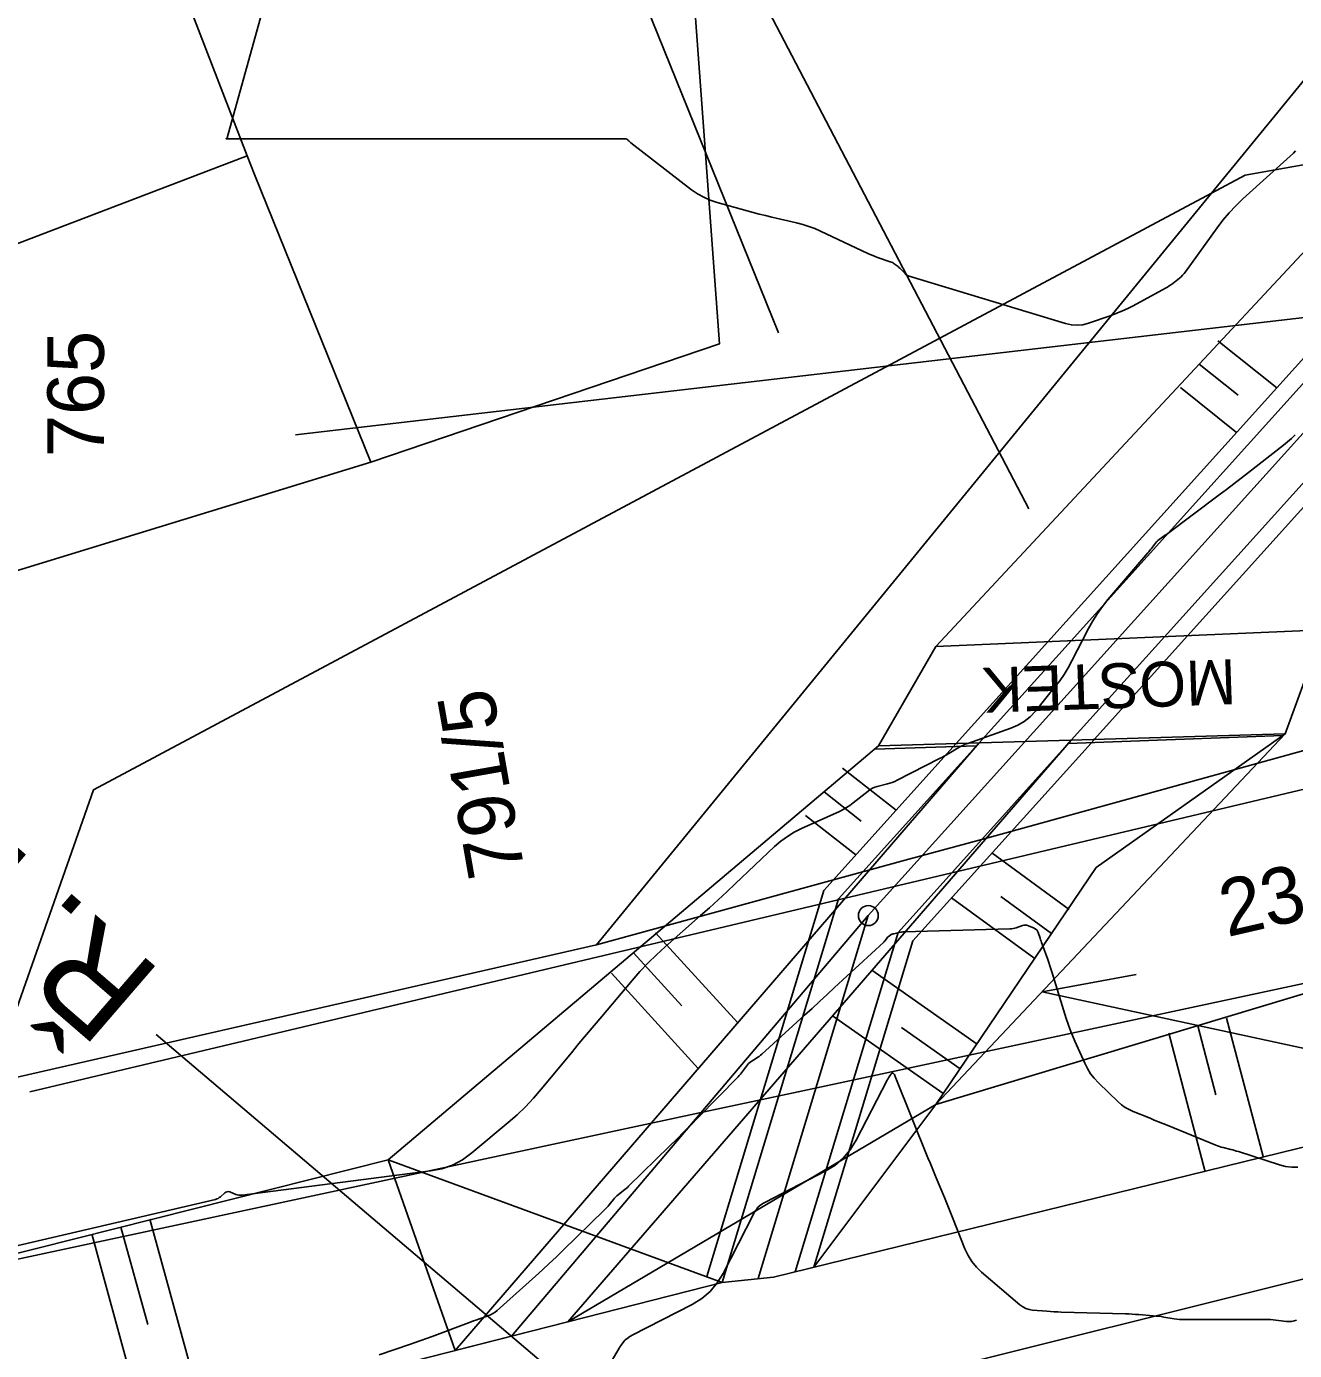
# Model space of a CAD drawing. Extents: x -534481 to -534262, y -1190577 to -1190138.
# Drawn here: x -534420.76 to -534401.7, y -1190524.99 to -1190505.1 of the extents above; entities that cross this region are included whole.
import ezdxf

# ---------------------------------------------------------------- set-up
doc = ezdxf.new("R2010")
doc.units = 0
for name, color, linetype in [('_přístup', 7, 'Continuous'), ('Bonity', 7, 'Continuous'), ('Definiční body', 7, 'Continuous'), ('Polygon budovy', 7, 'Continuous'), ('Vrstva 18', 7, 'Continuous'), ('Vrstva 19', 7, 'Continuous'), ('Vrstva 31', 7, 'Continuous'), ('Vrstva 32', 7, 'Continuous'), ('Vrstva 35', 7, 'Continuous'), ('Vrstva 36', 7, 'Continuous'), ('Vrstva 37', 7, 'Continuous'), ('Vrstva 41', 7, 'Continuous'), ('Vrstva 45', 7, 'Continuous'), ('Vrstva 58', 7, 'Continuous'), ('Značky bodu BP', 7, 'Continuous')]:
    doc.layers.add(name, color=color, linetype=linetype)

msp = doc.modelspace()

# ---------------------------------------------------------------- linework, layer by layer
at = {"layer": '_přístup'}
msp.add_lwpolyline([(-534437.347, -1190471.884), (-534433.314, -1190474.1), (-534423.794, -1190480.783), (-534415.053, -1190495.863), (-534409.457, -1190509.706)], dxfattribs=at)
at = {"layer": 'Bonity'}
for p, q in [((-534408.105, -1190518.46), (-534413.469, -1190524.777)), ((-534422.24, -1190529.075), (-534398.624, -1190523.185))]:
    msp.add_line(p, q, dxfattribs=at)
for points in [[(-534408.105, -1190518.46), (-534393.616, -1190502.389), (-534391.346, -1190496.962), (-534392.763, -1190488.017), (-534396.655, -1190477.752), (-534402.513, -1190464.283), (-534404.757, -1190456.741), (-534408.311, -1190433.088), (-534409.248, -1190427.879), (-534409.316, -1190416.054), (-534409.076, -1190409.418), (-534409.868, -1190391.439)], [(-534409.76, -1190523.914), (-534408.105, -1190518.46)]]:
    msp.add_lwpolyline(points, dxfattribs=at)
at = {"layer": 'Definiční body'}
for p, q in [((-534402.95, -1190507.61), (-534395.53, -1190498.55)), ((-534425.14, -1190509.99), (-534417.44, -1190507.05)), ((-534412.19, -1190518.9), (-534402.95, -1190507.61)), ((-534423.46, -1190514.06), (-534415.58, -1190511.65)), ((-534421.3, -1190520.98), (-534412.19, -1190518.9))]:
    msp.add_line(p, q, dxfattribs=at)
for points in [[(-534417.44, -1190507.05), (-534418.68, -1190503.83), (-534419, -1190502.99), (-534420.25, -1190499.72)], [(-534415.58, -1190511.65), (-534410.34, -1190509.87), (-534410.71, -1190504.84), (-534404.16, -1190502.37)], [(-534389.63, -1190505.06), (-534396.5, -1190506.28), (-534398.08, -1190506.56), (-534402.44, -1190507.34), (-534402.95, -1190507.61)], [(-534415.58, -1190511.65), (-534417.33, -1190507.33), (-534417.44, -1190507.05)], [(-534421.3, -1190520.98), (-534419.75, -1190516.57), (-534402.95, -1190507.61)], [(-534378.833, -1190515.085), (-534383.27, -1190515.56), (-534409.16, -1190521.11), (-534410.57, -1190521.41), (-534422.34, -1190523.93)], [(-534401.56, -1190515.98), (-534406.2, -1190517.26), (-534407.55, -1190517.63), (-534412.19, -1190518.9)]]:
    msp.add_lwpolyline(points, dxfattribs=at)
at = {"layer": 'Vrstva 18'}
for points in [[(-534416.759, -1190503.239), (-534417.74, -1190506.779), (-534417.742, -1190506.785), (-534417.745, -1190506.789), (-534417.75, -1190506.791), (-534417.756, -1190506.792), (-534417.737, -1190506.792), (-534417.73, -1190506.792), (-534411.753, -1190506.792), (-534411.748, -1190506.792), (-534411.744, -1190506.793), (-534411.739, -1190506.795), (-534411.736, -1190506.797), (-534411.721, -1190506.809), (-534411.713, -1190506.815), (-534411.706, -1190506.821), (-534411.691, -1190506.837), (-534411.683, -1190506.844), (-534411.675, -1190506.851), (-534410.762, -1190507.556), (-534410.673, -1190507.618), (-534410.579, -1190507.671), (-534410.48, -1190507.714), (-534410.377, -1190507.748), (-534409.928, -1190507.873), (-534409.835, -1190507.899), (-534409.743, -1190507.923), (-534409.65, -1190507.946), (-534409.556, -1190507.968), (-534409.183, -1190508.055), (-534409.091, -1190508.079), (-534409, -1190508.107), (-534408.911, -1190508.141), (-534408.823, -1190508.179), (-534408.11, -1190508.515), (-534408.075, -1190508.531), (-534408.039, -1190508.546), (-534408.002, -1190508.56), (-534407.965, -1190508.574), (-534407.776, -1190508.639), (-534407.76, -1190508.645), (-534407.744, -1190508.652), (-534407.729, -1190508.661), (-534407.715, -1190508.671), (-534407.659, -1190508.712), (-534407.646, -1190508.723), (-534407.632, -1190508.734), (-534407.62, -1190508.746), (-534407.607, -1190508.758), (-534407.552, -1190508.817), (-534407.539, -1190508.829), (-534407.524, -1190508.84), (-534407.507, -1190508.849), (-534407.489, -1190508.856), (-534405.14, -1190509.568), (-534405.053, -1190509.588), (-534404.967, -1190509.593), (-534404.882, -1190509.584), (-534404.796, -1190509.562), (-534404.454, -1190509.444), (-534404.37, -1190509.413), (-534404.287, -1190509.378), (-534404.205, -1190509.34), (-534404.125, -1190509.299), (-534403.639, -1190509.037), (-534403.611, -1190509.021), (-534403.583, -1190509.003), (-534403.557, -1190508.985), (-534403.531, -1190508.965), (-534403.429, -1190508.885), (-534403.405, -1190508.864), (-534403.382, -1190508.841), (-534403.36, -1190508.817), (-534403.34, -1190508.792), (-534402.865, -1190508.131), (-534402.777, -1190508.015), (-534402.683, -1190507.903), (-534402.583, -1190507.797), (-534402.477, -1190507.696), (-534401.716, -1190507.007), (-534401.683, -1190506.973)], [(-534415.454, -1190525.058), (-534414.999, -1190524.903), (-534414.913, -1190524.873), (-534414.829, -1190524.843), (-534414.744, -1190524.813), (-534414.659, -1190524.781), (-534414.112, -1190524.577), (-534414.075, -1190524.563), (-534414.038, -1190524.55), (-534414.001, -1190524.536), (-534413.964, -1190524.523), (-534413.817, -1190524.471), (-534413.781, -1190524.456), (-534413.747, -1190524.438), (-534413.715, -1190524.417), (-534413.685, -1190524.392), (-534413.109, -1190523.879), (-534413.003, -1190523.784), (-534412.899, -1190523.688), (-534412.796, -1190523.591), (-534412.695, -1190523.492), (-534412.069, -1190522.88), (-534412.051, -1190522.862), (-534412.034, -1190522.843), (-534412.017, -1190522.824), (-534412, -1190522.805), (-534411.935, -1190522.724), (-534411.918, -1190522.705), (-534411.901, -1190522.687), (-534411.883, -1190522.67), (-534411.863, -1190522.654), (-534411.783, -1190522.592), (-534411.763, -1190522.576), (-534411.744, -1190522.56), (-534411.725, -1190522.543), (-534411.707, -1190522.525), (-534411.092, -1190521.924), (-534410.984, -1190521.818), (-534410.876, -1190521.711), (-534410.769, -1190521.604), (-534410.663, -1190521.495), (-534410.062, -1190520.881), (-534410.045, -1190520.862), (-534410.028, -1190520.843), (-534410.012, -1190520.824), (-534409.997, -1190520.803), (-534409.936, -1190520.72), (-534409.921, -1190520.701), (-534409.904, -1190520.684), (-534409.886, -1190520.668), (-534409.866, -1190520.654), (-534409.784, -1190520.602), (-534409.764, -1190520.589), (-534409.744, -1190520.575), (-534409.725, -1190520.559), (-534409.707, -1190520.543), (-534409.063, -1190519.957), (-534408.95, -1190519.854), (-534408.837, -1190519.75), (-534408.725, -1190519.646), (-534408.612, -1190519.542), (-534407.874, -1190518.859), (-534407.866, -1190518.851), (-534407.859, -1190518.844), (-534407.853, -1190518.836), (-534407.847, -1190518.828), (-534407.822, -1190518.793), (-534407.816, -1190518.786), (-534407.809, -1190518.779), (-534407.801, -1190518.773), (-534407.793, -1190518.767), (-534407.76, -1190518.746), (-534407.751, -1190518.741), (-534407.742, -1190518.737), (-534407.733, -1190518.734), (-534407.724, -1190518.732), (-534407.639, -1190518.713), (-534407.621, -1190518.71), (-534407.604, -1190518.707), (-534407.586, -1190518.705), (-534407.569, -1190518.705), (-534405.977, -1190518.661), (-534405.953, -1190518.659), (-534405.929, -1190518.656), (-534405.905, -1190518.65), (-534405.882, -1190518.643), (-534405.788, -1190518.61), (-534405.766, -1190518.604), (-534405.743, -1190518.602), (-534405.721, -1190518.605), (-534405.699, -1190518.613), (-534405.611, -1190518.651), (-534405.591, -1190518.662), (-534405.575, -1190518.676), (-534405.563, -1190518.693), (-534405.554, -1190518.714), (-534405.525, -1190518.801), (-534405.517, -1190518.823), (-534405.51, -1190518.844), (-534405.502, -1190518.866), (-534405.494, -1190518.888), (-534405.408, -1190519.121), (-534405.391, -1190519.167), (-534405.375, -1190519.214), (-534405.36, -1190519.261), (-534405.345, -1190519.307), (-534405.131, -1190520.004), (-534405.103, -1190520.091), (-534405.072, -1190520.177), (-534405.038, -1190520.261), (-534405.002, -1190520.345), (-534404.853, -1190520.678), (-534404.812, -1190520.759), (-534404.764, -1190520.835), (-534404.709, -1190520.905), (-534404.647, -1190520.971), (-534404.35, -1190521.257), (-534404.299, -1190521.302), (-534404.244, -1190521.341), (-534404.186, -1190521.375), (-534404.124, -1190521.403), (-534403.87, -1190521.505), (-534403.807, -1190521.531), (-534403.743, -1190521.557), (-534403.68, -1190521.582), (-534403.616, -1190521.608), (-534402.884, -1190521.909), (-534402.857, -1190521.919), (-534402.829, -1190521.929), (-534402.801, -1190521.938), (-534402.772, -1190521.945), (-534402.658, -1190521.973), (-534402.629, -1190521.98), (-534402.601, -1190521.988), (-534402.573, -1190521.997), (-534402.544, -1190522.005), (-534401.926, -1190522.206), (-534401.834, -1190522.229), (-534401.742, -1190522.239), (-534401.649, -1190522.237)]]:
    msp.add_lwpolyline(points, dxfattribs=at)
at = {"layer": 'Vrstva 19'}
for points in [[(-534401.691, -1190511.239), (-534401.747, -1190511.292), (-534401.805, -1190511.343), (-534401.865, -1190511.392), (-534402.393, -1190511.807), (-534402.502, -1190511.892), (-534402.611, -1190511.976), (-534402.721, -1190512.06), (-534402.831, -1190512.142), (-534403.626, -1190512.734), (-534403.652, -1190512.753), (-534403.678, -1190512.773), (-534403.754, -1190512.827), (-534403.757, -1190512.83), (-534403.76, -1190512.834), (-534403.772, -1190512.848), (-534403.851, -1190512.946), (-534403.864, -1190512.962), (-534403.878, -1190512.979), (-534403.892, -1190512.996), (-534403.906, -1190513.012), (-534404.505, -1190513.714), (-534404.586, -1190513.816), (-534404.662, -1190513.922), (-534404.731, -1190514.032), (-534404.794, -1190514.146), (-534405.045, -1190514.636), (-534405.101, -1190514.739), (-534405.162, -1190514.838), (-534405.228, -1190514.934), (-534405.3, -1190515.026), (-534405.595, -1190515.389), (-534405.674, -1190515.473), (-534405.761, -1190515.544), (-534405.858, -1190515.602), (-534405.964, -1190515.647), (-534406.612, -1190515.873), (-534406.649, -1190515.887), (-534406.686, -1190515.903), (-534406.722, -1190515.921), (-534406.757, -1190515.941), (-534406.896, -1190516.025), (-534406.931, -1190516.045), (-534406.966, -1190516.065), (-534407.001, -1190516.085), (-534407.037, -1190516.103), (-534407.673, -1190516.428), (-534407.709, -1190516.445), (-534407.745, -1190516.459), (-534407.781, -1190516.472), (-534407.819, -1190516.483), (-534407.971, -1190516.521), (-534408.008, -1190516.533), (-534408.043, -1190516.548), (-534408.077, -1190516.567), (-534408.108, -1190516.59), (-534408.332, -1190516.769), (-534408.381, -1190516.805), (-534408.431, -1190516.838), (-534408.484, -1190516.868), (-534408.538, -1190516.895), (-534409.107, -1190517.152), (-534409.217, -1190517.208), (-534409.322, -1190517.272), (-534409.42, -1190517.344), (-534409.514, -1190517.425), (-534410.104, -1190517.984), (-534410.233, -1190518.105), (-534410.363, -1190518.224), (-534410.494, -1190518.343), (-534410.626, -1190518.46), (-534411.159, -1190518.929), (-534411.29, -1190519.048), (-534411.416, -1190519.172), (-534411.537, -1190519.3), (-534411.654, -1190519.433), (-534412.112, -1190519.975), (-534412.227, -1190520.111), (-534412.341, -1190520.247), (-534412.454, -1190520.383), (-534412.567, -1190520.52), (-534413.019, -1190521.069), (-534413.135, -1190521.203), (-534413.257, -1190521.331), (-534413.384, -1190521.454), (-534413.517, -1190521.57), (-534414.063, -1190522.025), (-534414.204, -1190522.127), (-534414.355, -1190522.207), (-534414.516, -1190522.263), (-534414.687, -1190522.297), (-534417.517, -1190522.66), (-534417.54, -1190522.661), (-534417.564, -1190522.66), (-534417.586, -1190522.656), (-534417.609, -1190522.648), (-534417.702, -1190522.612), (-534417.722, -1190522.607), (-534417.741, -1190522.608), (-534417.759, -1190522.614), (-534417.776, -1190522.626), (-534417.842, -1190522.684), (-534417.859, -1190522.697), (-534417.877, -1190522.708), (-534417.897, -1190522.716), (-534417.918, -1190522.723), (-534421.486, -1190523.555)], [(-534401.669, -1190524.536), (-534401.706, -1190524.549), (-534401.744, -1190524.556), (-534401.783, -1190524.559), (-534401.822, -1190524.556), (-534401.981, -1190524.537), (-534402.021, -1190524.533), (-534402.061, -1190524.53), (-534402.1, -1190524.528), (-534402.14, -1190524.527), (-534403.348, -1190524.529), (-534403.388, -1190524.529), (-534403.428, -1190524.526), (-534403.467, -1190524.522), (-534403.507, -1190524.517), (-534403.664, -1190524.491), (-534403.704, -1190524.485), (-534403.743, -1190524.48), (-534403.783, -1190524.476), (-534403.823, -1190524.472), (-534404.042, -1190524.454), (-534404.092, -1190524.451), (-534404.142, -1190524.448), (-534404.191, -1190524.445), (-534404.241, -1190524.443), (-534405.205, -1190524.417), (-534405.259, -1190524.415), (-534405.313, -1190524.413), (-534405.367, -1190524.409), (-534405.421, -1190524.405), (-534405.636, -1190524.385), (-534405.688, -1190524.376), (-534405.737, -1190524.36), (-534405.783, -1190524.337), (-534405.826, -1190524.306), (-534406.402, -1190523.817), (-534406.481, -1190523.742), (-534406.55, -1190523.658), (-534406.607, -1190523.566), (-534406.654, -1190523.466), (-534406.84, -1190522.994), (-534406.87, -1190522.92), (-534406.9, -1190522.845), (-534406.931, -1190522.77), (-534406.962, -1190522.696), (-534407.086, -1190522.398), (-534407.117, -1190522.324), (-534407.148, -1190522.25), (-534407.178, -1190522.175), (-534407.209, -1190522.1), (-534407.693, -1190520.901), (-534407.702, -1190520.879), (-534407.714, -1190520.849), (-534407.717, -1190520.845), (-534407.719, -1190520.841), (-534407.725, -1190520.832), (-534407.728, -1190520.83), (-534407.732, -1190520.828), (-534407.739, -1190520.825), (-534407.743, -1190520.824), (-534407.746, -1190520.826), (-534407.761, -1190520.839), (-534407.766, -1190520.845), (-534407.771, -1190520.851), (-534407.802, -1190520.898), (-534407.808, -1190520.907), (-534407.814, -1190520.916), (-534407.819, -1190520.925), (-534407.824, -1190520.935), (-534408.288, -1190521.836), (-534408.376, -1190521.98), (-534408.483, -1190522.105), (-534408.608, -1190522.212), (-534408.752, -1190522.3), (-534409.652, -1190522.763), (-534409.662, -1190522.768), (-534409.671, -1190522.774), (-534409.68, -1190522.779), (-534409.689, -1190522.785), (-534409.74, -1190522.819), (-534409.745, -1190522.823), (-534409.758, -1190522.836), (-534409.765, -1190522.843), (-534409.769, -1190522.848), (-534409.803, -1190522.898), (-534409.809, -1190522.907), (-534409.814, -1190522.916), (-534409.819, -1190522.926), (-534409.825, -1190522.935), (-534410.288, -1190523.836), (-534410.376, -1190523.979), (-534410.483, -1190524.105), (-534410.608, -1190524.212), (-534410.752, -1190524.3), (-534411.652, -1190524.763), (-534411.662, -1190524.768), (-534411.671, -1190524.773), (-534411.68, -1190524.779), (-534411.689, -1190524.785), (-534411.736, -1190524.816), (-534411.743, -1190524.821), (-534411.749, -1190524.827), (-534411.762, -1190524.839), (-534411.768, -1190524.845), (-534411.774, -1190524.851), (-534411.822, -1190524.917), (-534411.831, -1190524.93), (-534411.84, -1190524.942), (-534411.848, -1190524.955), (-534411.856, -1190524.968), (-534412.343, -1190525.794)]]:
    msp.add_lwpolyline(points, dxfattribs=at)
at = {"layer": 'Vrstva 31'}
for p, q in [((-534411.303, -1190518.717), (-534410.068, -1190520.07)), ((-534411.635, -1190519.02), (-534410.91, -1190519.815)), ((-534411.967, -1190519.323), (-534410.66, -1190520.756)), ((-534406.467, -1190520.393), (-534408.05, -1190519.282)), ((-534405.492, -1190519.605), (-534404.082, -1190519.345)), ((-534405.492, -1190519.605), (-534380.58, -1190524.995)), ((-534406.984, -1190521.13), (-534408.642, -1190519.966)), ((-534406.725, -1190520.761), (-534407.606, -1190520.143))]:
    msp.add_line(p, q, dxfattribs=at)
msp.add_lwpolyline([(-534405.695, -1190512.351), (-534434.703, -1190456.89), (-534411.68, -1190394.248)], dxfattribs=at)
at = {"layer": 'Vrstva 32'}
for p, q in [((-534405.1, -1190515.876), (-534401.878, -1190515.757)), ((-534406.439, -1190515.865), (-534414.316, -1190524.993)), ((-534405.056, -1190515.825), (-534412.621, -1190524.561)), ((-534406.479, -1190515.912), (-534408.011, -1190515.961)), ((-534408.133, -1190529.308), (-534418.805, -1190520.246)), ((-534414.316, -1190524.993), (-534412.621, -1190524.561))]:
    msp.add_line(p, q, dxfattribs=at)
for points in [[(-534401.84, -1190515.73), (-534407.09, -1190521.3), (-534407.09, -1190521.3), (-534412.621, -1190524.561)], [(-534407.95, -1190515.91), (-534415.32, -1190522.13), (-534414.316, -1190524.993)]]:
    msp.add_lwpolyline(points, dxfattribs=at)
at = {"layer": 'Vrstva 35'}
for p, q in [((-534407.09, -1190514.42), (-534400.591, -1190507.452)), ((-534416.715, -1190511.238), (-534390.485, -1190508.189)), ((-534404.68, -1190517.74), (-534401.84, -1190515.73)), ((-534415.32, -1190522.13), (-534407.95, -1190515.91)), ((-534407.09, -1190521.3), (-534404.68, -1190517.74)), ((-534398.2, -1190518.62), (-534407.09, -1190521.3)), ((-534408.924, -1190523.741), (-534407.09, -1190521.3)), ((-534425.13, -1190524.6), (-534415.32, -1190522.13)), ((-534415.32, -1190522.13), (-534410.3, -1190523.97))]:
    msp.add_line(p, q, dxfattribs=at)
for points in [[(-534405.407, -1190514.348), (-534394.258, -1190501.982), (-534392.12, -1190496.869), (-534393.492, -1190488.211), (-534397.35, -1190478.035), (-534403.219, -1190464.54), (-534405.491, -1190456.905), (-534409.051, -1190433.21), (-534409.998, -1190427.948), (-534410.066, -1190416.042), (-534409.827, -1190409.421), (-534410.645, -1190390.84)], [(-534405.057, -1190514.333), (-534394.044, -1190502.118), (-534391.862, -1190496.9), (-534393.249, -1190488.146), (-534397.118, -1190477.94), (-534402.983, -1190464.455), (-534405.247, -1190456.85), (-534408.804, -1190433.17), (-534409.748, -1190427.925), (-534409.816, -1190416.046), (-534409.577, -1190409.42), (-534410.397, -1190390.795)], [(-534403.656, -1190514.273), (-534393.187, -1190502.661), (-534390.83, -1190497.024), (-534392.278, -1190487.888), (-534396.191, -1190477.563), (-534402.042, -1190464.111), (-534404.268, -1190456.632), (-534407.818, -1190433.007), (-534408.749, -1190427.833), (-534408.816, -1190416.061), (-534408.576, -1190409.416), (-534409.363, -1190391.537)], [(-534403.306, -1190514.257), (-534392.973, -1190502.796), (-534390.572, -1190497.055), (-534392.035, -1190487.824), (-534395.96, -1190477.469), (-534401.807, -1190464.025), (-534404.023, -1190456.578), (-534407.571, -1190432.966), (-534408.499, -1190427.81), (-534408.566, -1190416.065), (-534408.326, -1190409.415), (-534409.111, -1190391.586)], [(-534410.534, -1190523.884), (-534408.774, -1190518.082), (-534406.785, -1190515.876)], [(-534410.299, -1190523.97), (-534408.551, -1190518.208), (-534406.439, -1190515.865)], [(-534409.206, -1190523.811), (-534407.659, -1190518.712), (-534405.056, -1190515.825)], [(-534408.924, -1190523.741), (-534407.436, -1190518.838), (-534404.713, -1190515.818)], [(-534422.71, -1190527.13), (-534410.3, -1190523.97), (-534409.53, -1190523.89), (-534398.67, -1190521.23)]]:
    msp.add_lwpolyline(points, dxfattribs=at)
at = {"layer": 'Vrstva 36'}
for p, q in [((-534402.852, -1190509.826), (-534401.968, -1190510.533)), ((-534403.133, -1190510.178), (-534402.548, -1190510.645)), ((-534403.414, -1190510.529), (-534402.572, -1190511.202)), ((-534408.492, -1190516.248), (-534407.689, -1190516.879)), ((-534408.77, -1190516.602), (-534408.211, -1190517.042)), ((-534409.048, -1190516.956), (-534408.293, -1190517.549)), ((-534405.086, -1190518.368), (-534406.248, -1190517.52)), ((-534405.351, -1190518.731), (-534406.116, -1190518.173)), ((-534405.617, -1190519.095), (-534406.853, -1190518.192)), ((-534403.155, -1190520.114), (-534402.881, -1190521.154)), ((-534402.72, -1190519.999), (-534402.172, -1190522.08)), ((-534403.59, -1190520.228), (-534403.043, -1190522.309)), ((-534419.336, -1190523.141), (-534418.934, -1190524.604)), ((-534418.902, -1190523.022), (-534418.098, -1190525.947)), ((-534419.77, -1190523.261), (-534418.966, -1190526.185))]:
    msp.add_line(p, q, dxfattribs=at)
at = {"layer": 'Vrstva 37'}
msp.add_circle((-534408.105, -1190518.46), 0.15, dxfattribs=at)
at = {"layer": 'Vrstva 41'}
for points in [[(-534406.785, -1190515.876), (-534405.407, -1190514.348)], [(-534406.439, -1190515.865), (-534405.057, -1190514.333)], [(-534405.056, -1190515.825), (-534403.656, -1190514.273)], [(-534404.71, -1190515.815), (-534403.306, -1190514.257)]]:
    msp.add_lwpolyline(points, dxfattribs=at)
at = {"layer": 'Vrstva 58'}
msp.add_lwpolyline([(-534420.706, -1190521.11), (-534390.696, -1190513.981)], dxfattribs=at)
at = {"layer": 'Značky bodu BP'}
msp.add_lwpolyline([(-534407.09, -1190514.42), (-534407.09, -1190514.42), (-534407.95, -1190515.91), (-534401.84, -1190515.73), (-534401.27, -1190514.17), (-534407.09, -1190514.42)], dxfattribs=at)

# ---------------------------------------------------------------- texts
at = {"layer": 'Polygon budovy'}
for s, rotation, p in [('765', 90, (-534419.593, -1190511.573)), ('791/5', 100, (-534413.263, -1190517.812)), ('2302/511', 13, (-534402.712, -1190518.785))]:
    msp.add_text(s, height=0.85, rotation=rotation, dxfattribs=at).set_placement(p)
at = {"layer": 'Vrstva 31'}
msp.add_text('Ř. KM 0,000', height=1.5, rotation=139.2051, dxfattribs=at).set_placement((-534418.699, -1190519.326))
at = {"layer": 'Vrstva 45'}
msp.add_text('MOSTEK', height=0.675, rotation=181.9803, dxfattribs=at).set_placement((-534402.592, -1190514.608))

doc.saveas('drawing.dxf')
